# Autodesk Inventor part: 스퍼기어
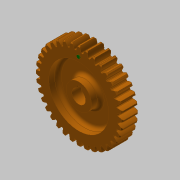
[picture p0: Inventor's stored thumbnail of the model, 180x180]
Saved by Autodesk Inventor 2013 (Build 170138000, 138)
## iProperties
Created: 2019-01
Part Number: 스퍼기어
Material: 알루미늄 6061
Document SubType Name: Modeling
Designer: mduedu
Density: 2.71 g/cm^3
Mass: 116.094 g
Surface Area: 165.902 cm^2
Volume: 42.8393 cm^3
Author: mduedu
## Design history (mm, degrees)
sketch "스케치1"
  geometry: C1 r 33.5 at (0, 0); C2 r 36 at (0, 0); C3 r 38 at (0, 0); 1 further point
  constraints: 3 centre point, 3 coincident
  dimensions: "d0" = 67 diameter of C1; "d2" = 72 diameter of C2; "d3" = 76 diameter of C3
extrude "돌출1" new body sketch "스케치1" distance "d4" = 14; taper "d5" = 0 deg
sketch "스케치2"
  geometry: L1 (0, 0)-(-38, 0); L2 (0, 0)-(0, 38); L3 (-0.57, 0)-(-0.57, 37.996); L4 (-1.57, 0)-(-1.57, 35.966); L5 (-2.07, 0)-(-2.07, 33.436); A1 r 38 centre (0, 0) between (-38, 0) and (0, 38) reference; A2 r 9.246 centre (7.162, 32.926) between (-0.57, 37.996) and (-2.07, 33.436); A3 r 9.246 centre (-7.162, 32.926) between (2.07, 33.436) and (0.57, 37.996); A4 r 33.5 centre (0, 0) between (2.07, 33.436) and (-2.07, 33.436); A5 r 38 centre (0, 0) between (0.57, 37.996) and (-0.57, 37.996); 2 further points
  constraints: 12 point on circle, 10 end point, 4 centre point, 3 parallel, 3 symmetric about line, 2 coincident, 1 horizontal, 1 perpendicular, 5 other
  dimensions: "d6" = 0.5 distance between parallel lines of L4 L5; "d8" = 1 distance between parallel lines of L3 L4; "d9" = 1.57 distance between parallel lines of L2 L4
extrude "돌출2" join sketch "스케치2" stored distance "d10" = 14; taper "d11" = 0 deg
chamfer "모따기1" distance "d12" = 1; stored, may be unused: second distance "d13" = 2, angle "d14" = 45 deg
fillet "모깎기1" dims "d15" = 0.5
sketch "스케치3"
  geometry: C1 r 11 at (0, 0); 1 further point
  constraints: 1 centre point, 1 coincident
  dimensions: "d19" = 22 diameter of C1
extrude "돌출3" join sketch "스케치3" distance "d20" = 6; taper "d21" = 0 deg
fillet "모깎기2" dims "d22" = 3
sketch "스케치4"
  geometry: C1 r 11 at (0, 0); C2 r 26 at (0, 0); 1 further point
  constraints: 2 centre point, 2 coincident
  dimensions: "d23" = 22 diameter of C1; "d24" = 52 diameter of C2
extrude "돌출4" cut sketch "스케치4" distance "d25" = 8; taper "d26" = 0 deg
fillet "모깎기3" dims "d27" = 3
sketch "스케치5" dims "d28" = 60
  geometry: C1 r 1.5 at (0, 30); 2 further points
  constraints: 2 vertical alignment, 1 centre point, 1 coincident, 2 other
  dimensions: "d29" = 3 diameter of C1
extrude "돌출5" join sketch "스케치5" distance "d30" = 0.5; taper "d31" = 0 deg
sketch "스케치6"
  geometry: L1 (-2, 5.657)-(2, 5.657); L2 (2, 5.657)-(2, 7.8); L3 (2, 7.8)-(-2, 7.8); L4 (-2, 7.8)-(-2, 5.657); A1 r 6 centre (0, 0) between (-2, 5.657) and (2, 5.657); 1 further point
  constraints: 8 end point, 2 parallel, 2 point on circle, 1 centre point, 1 coincident, 1 horizontal, 1 perpendicular
  dimensions: "d32" = 13.8 dimension on A1 L3; "d34" = 4 distance of L2.end L3.end; "d35" = 12 diameter of A1
extrude "돌출6" cut sketch "스케치6" stored distance "d36" = 0.5; taper "d37" = 0 deg
chamfer "모따기2" distance "d38" = 1; stored, may be unused: second distance "d39" = 2, angle "d40" = 45 deg
node "솔리드1"
pattern_circular "원형 패턴1" dims "d17" = 360 deg
